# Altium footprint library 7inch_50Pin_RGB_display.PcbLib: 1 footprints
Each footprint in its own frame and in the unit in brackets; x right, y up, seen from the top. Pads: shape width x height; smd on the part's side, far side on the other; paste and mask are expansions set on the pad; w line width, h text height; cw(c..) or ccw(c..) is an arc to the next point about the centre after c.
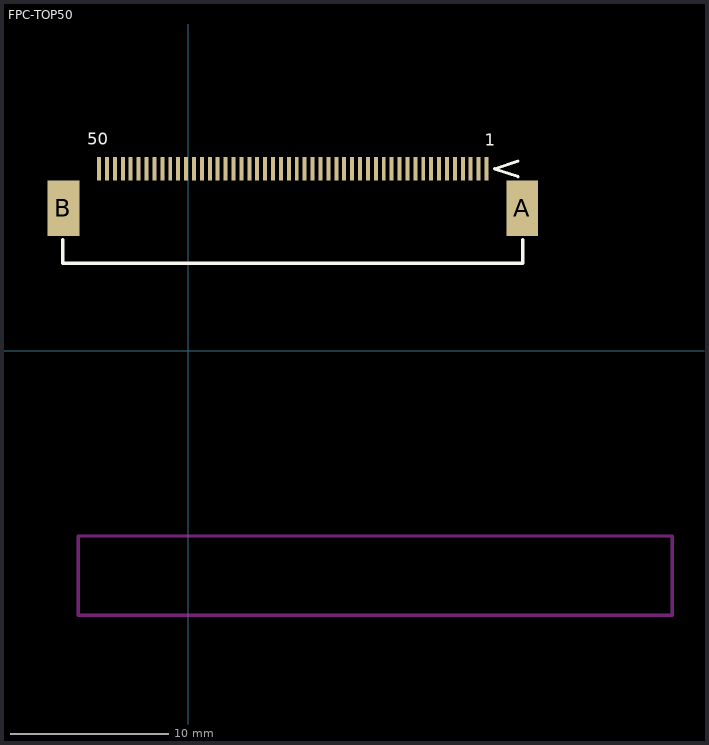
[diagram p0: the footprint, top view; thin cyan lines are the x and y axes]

## FPC-TOP50 [mm]
pads (52):
  rect 0.25x1.5 smd: 1(18.876,11.517) 2(18.376,11.517) 3(17.876,11.517) 4(17.376,11.517) 5(16.876,11.517) 6(16.376,11.517) 7(15.876,11.517) 8(15.376,11.517) 9(14.876,11.517) 10(14.376,11.517) 11(13.876,11.517) 12(13.376,11.517) 13(12.876,11.517) 14(12.376,11.517) 15(11.876,11.517) 16(11.376,11.517) 17(10.876,11.517) 18(10.376,11.517) 19(9.876,11.517) 20(9.376,11.517) 21(8.876,11.517) 22(8.376,11.517) 23(7.876,11.517) 24(7.376,11.517) 25(6.876,11.517) 26(6.376,11.517) 27(5.876,11.517) 28(5.376,11.517) 29(4.876,11.517) 30(4.376,11.517) 31(3.876,11.517) 32(3.376,11.517) 33(2.876,11.517) 34(2.376,11.517) 35(1.876,11.517) 36(1.376,11.517) 37(0.876,11.517) 38(0.376,11.517) 39(-0.124,11.517) 40(-0.624,11.517) 41(-1.124,11.517) 42(-1.624,11.517) 43(-2.124,11.517) 44(-2.624,11.517) 45(-3.124,11.517) 46(-3.624,11.517) 47(-4.124,11.517) 48(-4.624,11.517) 49(-5.124,11.517) 50(-5.624,11.517)
  rect 2x3.5 smd: A(21.126,9.017) B(-7.874,9.017)
Top Overlay:
  lines w0.2: 20.876,11.017 19.376,11.517 20.876,12.017
  lines w0.203: -7.921,7.047 -7.921,5.548 -3.43,5.548 21.162,5.548 21.162,7.047
  text "1" at 18.749,12.977 h0.76
  text "50" at -6.371,13.028 h0.76
Keep-Out Layer:
  lines w0.203: -6.936,-16.712 -6.936,-11.712 30.616,-11.712 30.616,-16.712 -6.936,-16.712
